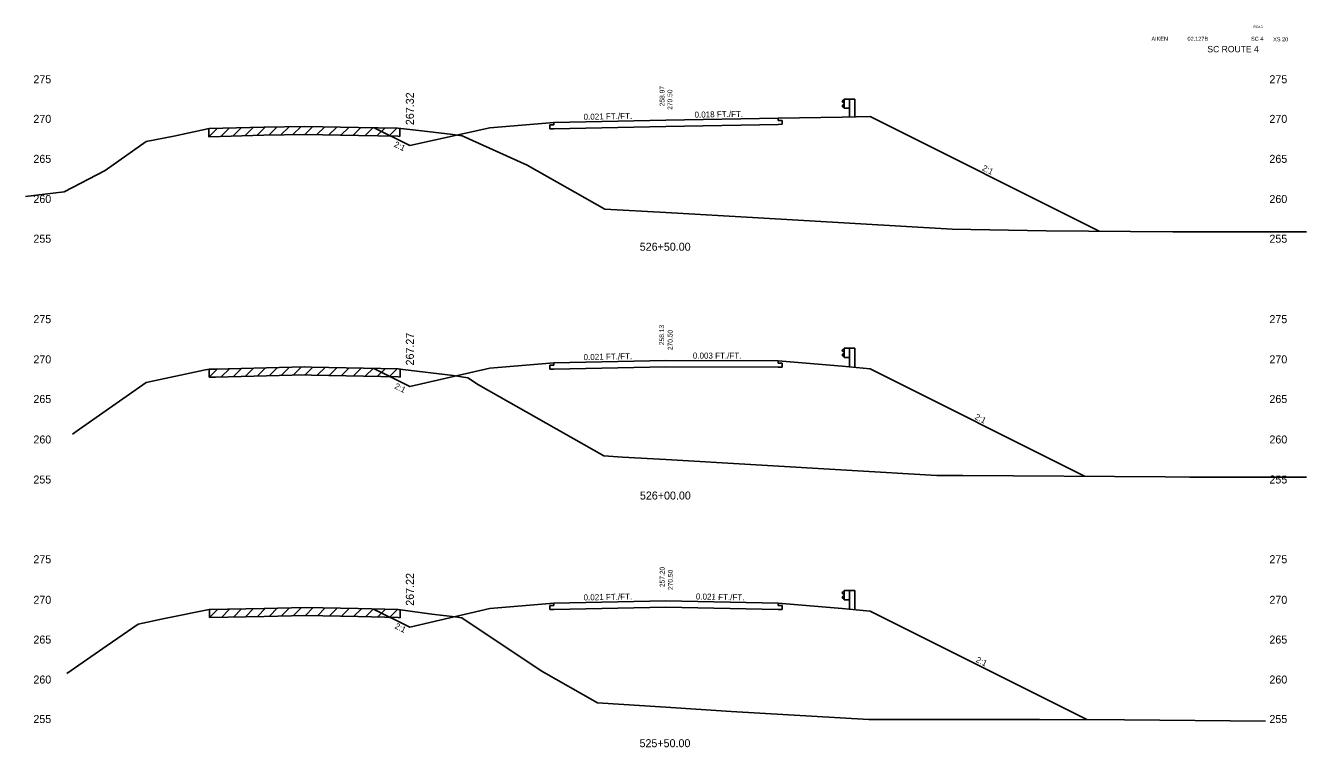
# Model space of a CAD drawing. Extents: x 883 to 1160, y 1002 to 4323.
# Drawn here: x 1000 to 1160, y 3197.2 to 3287.3 of the extents above; entities that cross this region are included whole.
import ezdxf

# ---------------------------------------------------------------- set-up
doc = ezdxf.new("R2010")
doc.units = 0
for name, color, linetype in [('Level 1', 7, 'Continuous'), ('Level 10', 7, 'Continuous'), ('Level 11', 7, 'Continuous'), ('Level 12', 7, 'Continuous'), ('Level 24', 7, 'Continuous'), ('Level 3', 7, 'Continuous'), ('Level 32', 7, 'Continuous'), ('Level 33', 7, 'Continuous'), ('Level 59', 7, 'Continuous'), ('Level 6', 7, 'Continuous'), ('Level 60', 7, 'Continuous'), ('Level 61', 7, 'Continuous'), ('Level 7', 7, 'Continuous')]:
    doc.layers.add(name, color=color, linetype=linetype)

msp = doc.modelspace()

# ---------------------------------------------------------------- linework, layer by layer
at = {"layer": 'Level 11'}
for p, q in [((1066, 3275.21), (1066, 3274.91)), ((1094, 3275.45), (1094, 3275.75)), ((1094.5, 3275.46), (1094, 3275.45)), ((1094.5, 3274.98), (1094.5, 3275.46)), ((1066, 3274.91), (1065.5, 3274.9)), ((1065.5, 3274.9), (1065.5, 3274.42)), ((1065.5, 3274.42), (1066, 3274.43)), ((1094, 3274.97), (1094.5, 3274.98)), ((1066, 3244.91), (1065.5, 3244.9)), ((1065.5, 3244.9), (1065.5, 3244.42)), ((1066, 3245.21), (1066, 3244.91)), ((1094, 3245.16), (1094, 3245.46)), ((1094.5, 3245.16), (1094, 3245.16)), ((1094.5, 3244.68), (1094.5, 3245.16)), ((1065.5, 3244.42), (1066, 3244.43)), ((1094, 3244.68), (1094.5, 3244.68)), ((1066, 3214.91), (1065.5, 3214.9)), ((1065.5, 3214.9), (1065.5, 3214.42)), ((1065.5, 3214.42), (1066, 3214.43)), ((1066, 3215.21), (1066, 3214.91)), ((1094, 3214.91), (1094, 3215.21)), ((1094.5, 3214.9), (1094, 3214.91)), ((1094, 3214.43), (1094.5, 3214.42)), ((1094.5, 3214.42), (1094.5, 3214.9))]:
    msp.add_line(p, q, dxfattribs=at)
at = {"layer": 'Level 12'}
for p, q in [((1080, 3274.72), (1066, 3274.43)), ((1094, 3274.97), (1080, 3274.72)), ((1080, 3244.72), (1066, 3244.43)), ((1094, 3244.68), (1080, 3244.72)), ((1080, 3214.72), (1066, 3214.43)), ((1094, 3214.43), (1080, 3214.72))]:
    msp.add_line(p, q, dxfattribs=at)
at = {"layer": 'Level 24'}
for p, q in [((1102.27, 3278.07), (1102, 3277.87)), ((1102, 3277.87), (1102, 3277.82)), ((1102, 3277.82), (1102.27, 3277.62)), ((1102, 3277.3), (1102.27, 3277.5)), ((1102, 3277.25), (1102, 3277.3)), ((1102.27, 3277.05), (1102, 3277.25)), ((1102.27, 3276.98), (1102.27, 3278.14)), ((1102.27, 3278.14), (1102.94, 3278.14)), ((1102.27, 3276.98), (1102.94, 3276.98)), ((1102.94, 3278.14), (1102.94, 3275.91)), ((1102.94, 3278.14), (1103.6, 3278.14)), ((1103.6, 3278.14), (1103.6, 3275.92)), ((1102.27, 3246.97), (1102, 3246.77)), ((1102, 3246.77), (1102, 3246.72)), ((1102, 3246.72), (1102.27, 3246.52)), ((1102.27, 3245.87), (1102.27, 3247.04)), ((1102.27, 3247.04), (1102.94, 3247.04)), ((1102.94, 3247.04), (1102.94, 3244.7)), ((1102.94, 3247.04), (1103.6, 3247.04)), ((1103.6, 3247.04), (1103.6, 3244.63)), ((1102, 3246.2), (1102.27, 3246.4)), ((1102, 3246.15), (1102, 3246.2)), ((1102.27, 3245.95), (1102, 3246.15)), ((1102.27, 3245.87), (1102.94, 3245.87)), ((1102.27, 3216.72), (1102, 3216.52)), ((1102, 3216.52), (1102, 3216.47)), ((1102, 3216.47), (1102.27, 3216.27)), ((1102, 3215.95), (1102.27, 3216.15)), ((1102.27, 3215.63), (1102.27, 3216.79)), ((1102.27, 3216.79), (1102.94, 3216.79)), ((1102.94, 3216.79), (1102.94, 3214.45)), ((1102.94, 3216.79), (1103.6, 3216.79)), ((1103.6, 3216.79), (1103.6, 3214.38)), ((1102, 3215.9), (1102, 3215.95)), ((1102.27, 3215.7), (1102, 3215.9)), ((1102.27, 3215.63), (1102.94, 3215.63))]:
    msp.add_line(p, q, dxfattribs=at)
at = {"layer": 'Level 59'}
for p, q in [((1066, 3275.21), (1080, 3275.5)), ((1080, 3275.5), (1094, 3275.75)), ((1066, 3245.21), (1080, 3245.5)), ((1080, 3245.5), (1094, 3245.46)), ((1066, 3215.21), (1080, 3215.5)), ((1080, 3215.5), (1094, 3215.21))]:
    msp.add_line(p, q, dxfattribs=at)
at = {"layer": 'Level 6'}
for p, q in [((1058, 3274.54), (1066, 3275.21)), ((1094, 3275.75), (1102, 3275.89)), ((1102, 3275.89), (1105.5, 3275.96)), ((1058, 3244.54), (1066, 3245.21)), ((1094, 3245.46), (1102, 3244.79)), ((1102, 3244.79), (1105.5, 3244.44)), ((1058, 3214.54), (1066, 3215.21)), ((1094, 3215.21), (1102, 3214.54)), ((1102, 3214.54), (1105.5, 3214.19))]:
    msp.add_line(p, q, dxfattribs=at)
at = {"layer": 'Level 60'}
for p, q in [((1018.52, 3273.51), (1022.92, 3274.44)), ((1022.92, 3274.44), (1029.75, 3274.61)), ((1029.75, 3274.61), (1034.9, 3274.73)), ((1034.9, 3274.73), (1041.6, 3274.58)), ((1041.6, 3274.58), (1046.5, 3274.5)), ((1046.5, 3274.5), (1049.48, 3274.16)), ((1049.48, 3274.16), (1053.37, 3273.7)), ((1053.37, 3273.7), (1054.52, 3273.53)), ((1009.93, 3269.23), (1015.08, 3272.84)), ((1015.08, 3272.84), (1018.52, 3273.51)), ((1054.52, 3273.53), (1062.67, 3269.87)), ((1004.81, 3266.54), (1009.93, 3269.23)), ((1062.67, 3269.87), (1072.36, 3264.4)), ((1000, 3265.99), (1004.81, 3266.54)), ((1072.36, 3264.4), (1080, 3263.97)), ((1080, 3263.97), (1091.5, 3263.32)), ((1091.5, 3263.32), (1115.77, 3261.9)), ((1115.77, 3261.9), (1127.49, 3261.69)), ((1127.49, 3261.69), (1143.33, 3261.57)), ((1143.33, 3261.57), (1154.78, 3261.57)), ((1154.78, 3261.57), (1160, 3261.57)), ((1015.07, 3242.76), (1022.25, 3244.27)), ((1022.25, 3244.27), (1022.91, 3244.4)), ((1022.91, 3244.4), (1023.74, 3244.42)), ((1023.74, 3244.42), (1034.89, 3244.7)), ((1034.89, 3244.7), (1035.71, 3244.68)), ((1035.71, 3244.68), (1046.56, 3244.44)), ((1046.56, 3244.44), (1047.11, 3244.36)), ((1047.11, 3244.36), (1053.4, 3243.62)), ((1053.4, 3243.62), (1055.25, 3243.34)), ((1055.25, 3243.34), (1056.57, 3242.46)), ((1006.75, 3236.93), (1015.07, 3242.76)), ((1056.57, 3242.46), (1072.24, 3233.6)), ((1005.84, 3236.3), (1006.75, 3236.93)), ((1072.24, 3233.6), (1074.55, 3233.45)), ((1074.55, 3233.45), (1080, 3233.13)), ((1080, 3233.13), (1113.82, 3231.15)), ((1113.82, 3231.15), (1117.08, 3231.16)), ((1117.08, 3231.16), (1142.36, 3230.97)), ((1142.36, 3230.97), (1145.43, 3230.95)), ((1145.43, 3230.95), (1160, 3230.95)), ((1022.93, 3214.4), (1029.79, 3214.55)), ((1029.79, 3214.55), (1034.94, 3214.68)), ((1034.94, 3214.68), (1041.54, 3214.52)), ((1041.54, 3214.52), (1046.56, 3214.41)), ((1046.56, 3214.41), (1050.76, 3213.82)), ((1014.04, 3212.6), (1017.36, 3213.3)), ((1017.36, 3213.3), (1022.93, 3214.4)), ((1050.76, 3213.82), (1053.65, 3213.48)), ((1053.65, 3213.48), (1054.49, 3213.36)), ((1054.49, 3213.36), (1064.39, 3206.76)), ((1010.19, 3209.91), (1014.04, 3212.6)), ((1005.16, 3206.43), (1010.19, 3209.91)), ((1064.39, 3206.76), (1071.45, 3202.76)), ((1071.45, 3202.76), (1080, 3202.2)), ((1080, 3202.2), (1088.15, 3201.66)), ((1088.15, 3201.66), (1105.32, 3200.66)), ((1105.32, 3200.66), (1126.68, 3200.7)), ((1126.68, 3200.7), (1137.28, 3200.62)), ((1137.28, 3200.62), (1154.91, 3200.49))]:
    msp.add_line(p, q, dxfattribs=at)
at = {"layer": 'Level 61'}
for p, q in [((1023.92, 3274.46), (1022.89, 3273.43)), ((1022.89, 3274.43), (1022.89, 3273.43)), ((1022.92, 3273.44), (1029.75, 3273.61)), ((1025.42, 3274.5), (1024.39, 3273.48)), ((1026.92, 3274.54), (1025.89, 3273.51)), ((1028.42, 3274.58), (1027.39, 3273.55)), ((1029.92, 3274.61), (1028.89, 3273.59)), ((1029.75, 3273.61), (1034.9, 3273.73)), ((1031.41, 3274.65), (1030.39, 3273.62)), ((1032.91, 3274.68), (1031.89, 3273.66)), ((1034.41, 3274.71), (1033.39, 3273.69)), ((1035.87, 3274.7), (1034.89, 3273.73)), ((1034.9, 3273.73), (1041.6, 3273.58)), ((1037.37, 3274.67), (1036.39, 3273.69)), ((1038.87, 3274.64), (1037.89, 3273.66)), ((1040.37, 3274.6), (1039.39, 3273.63)), ((1041.87, 3274.57), (1040.89, 3273.59)), ((1043.38, 3274.55), (1042.39, 3273.56)), ((1044.88, 3274.52), (1043.89, 3273.54)), ((1046.38, 3274.5), (1045.39, 3273.51)), ((1046.74, 3273.47), (1046.74, 3274.47)), ((1022.89, 3273.43), (1022.92, 3273.44)), ((1041.6, 3273.58), (1046.5, 3273.5)), ((1046.5, 3273.5), (1046.74, 3273.47)), ((1023.95, 3244.42), (1022.93, 3243.4)), ((1022.93, 3244.4), (1022.93, 3243.4)), ((1022.93, 3243.4), (1023.74, 3243.42)), ((1023.74, 3243.42), (1034.89, 3243.7)), ((1025.45, 3244.46), (1024.43, 3243.44)), ((1026.95, 3244.5), (1025.93, 3243.47)), ((1028.45, 3244.54), (1027.43, 3243.51)), ((1029.95, 3244.57), (1028.93, 3243.55)), ((1031.45, 3244.61), (1030.43, 3243.59)), ((1032.95, 3244.65), (1031.93, 3243.62)), ((1034.45, 3244.69), (1033.43, 3243.66)), ((1034.89, 3243.7), (1035.71, 3243.68)), ((1035.9, 3244.67), (1034.93, 3243.7)), ((1035.71, 3243.68), (1046.56, 3243.44)), ((1037.41, 3244.64), (1036.43, 3243.66)), ((1038.91, 3244.61), (1037.93, 3243.63)), ((1040.41, 3244.57), (1039.43, 3243.59)), ((1041.91, 3244.54), (1040.93, 3243.56)), ((1043.41, 3244.51), (1042.43, 3243.53)), ((1044.91, 3244.47), (1043.93, 3243.49)), ((1046.41, 3244.44), (1045.43, 3243.46)), ((1046.56, 3243.44), (1046.77, 3243.41)), ((1046.77, 3243.41), (1046.77, 3244.41)), ((1023.98, 3214.42), (1022.96, 3213.4)), ((1022.96, 3214.4), (1022.96, 3213.4)), ((1025.48, 3214.46), (1024.46, 3213.43)), ((1026.98, 3214.49), (1025.96, 3213.47)), ((1028.48, 3214.52), (1027.46, 3213.5)), ((1029.98, 3214.56), (1028.96, 3213.54)), ((1031.48, 3214.6), (1030.46, 3213.57)), ((1032.98, 3214.63), (1031.96, 3213.61)), ((1034.48, 3214.67), (1033.46, 3213.65)), ((1035.93, 3214.66), (1034.96, 3213.68)), ((1037.43, 3214.62), (1036.46, 3213.64)), ((1038.93, 3214.58), (1037.96, 3213.61)), ((1040.43, 3214.55), (1039.46, 3213.57)), ((1041.94, 3214.51), (1040.96, 3213.53)), ((1043.44, 3214.48), (1042.46, 3213.5)), ((1044.94, 3214.44), (1043.96, 3213.46)), ((1046.44, 3214.41), (1045.46, 3213.43)), ((1022.96, 3213.4), (1029.79, 3213.55)), ((1029.79, 3213.55), (1034.94, 3213.68)), ((1034.94, 3213.68), (1041.54, 3213.52)), ((1041.54, 3213.52), (1046.56, 3213.41)), ((1046.56, 3213.41), (1046.81, 3213.37)), ((1046.81, 3213.37), (1046.81, 3214.37))]:
    msp.add_line(p, q, dxfattribs=at)
at = {"layer": 'Level 7'}
for p, q in [((1105.5, 3275.96), (1134.13, 3261.64)), ((1043.54, 3274.54), (1048, 3272.32)), ((1048, 3272.32), (1058, 3274.54)), ((1043.52, 3244.5), (1048, 3242.27)), ((1048, 3242.27), (1058, 3244.54)), ((1105.5, 3244.44), (1132.29, 3231.05)), ((1043.48, 3214.47), (1048, 3212.22)), ((1048, 3212.22), (1058, 3214.54)), ((1105.5, 3214.19), (1132.57, 3200.66))]:
    msp.add_line(p, q, dxfattribs=at)

# ---------------------------------------------------------------- texts
at = {"layer": 'Level 1'}
for s, height, p in [('AIKEN', 0.5, (1140.64, 3285.41)), ('02.127B', 0.5, (1145.15, 3285.41)), ('SC 4', 0.5, (1153.09, 3285.41)), ('XS 20', 0.5, (1155.85, 3285.35)), ('SC ROUTE 4', 0.8, (1147.63, 3283.97)), ('526+50.00', 1, (1076.72, 3259.2)), ('526+00.00', 1, (1076.74, 3228.14)), ('525+50.00', 1, (1076.69, 3197.22))]:
    msp.add_text(s, height=height, dxfattribs=at).set_placement(p)
at = {"layer": 'Level 10'}
for s, p in [('258.97', (1079.81, 3277.23)), ('258.13', (1079.76, 3247.41)), ('257.20', (1079.82, 3217.21))]:
    msp.add_text(s, height=0.6, rotation=90, dxfattribs=at).set_placement(p)
at = {"layer": 'Level 3'}
for s, height, p in [('ROAD', 0.3, (1153.38, 3287)), (' 275', 1, (1000.6, 3280.11)), (' 275', 1, (1155.01, 3280.11)), (' 270', 1, (1000.6, 3275.16)), (' 270', 1, (1155.01, 3275.16)), (' 265', 1, (1000.6, 3270.17)), (' 265', 1, (1155.01, 3270.17)), (' 260', 1, (1000.6, 3265.16)), (' 260', 1, (1155.01, 3265.16)), (' 255', 1, (1000.6, 3260.2)), (' 255', 1, (1155.01, 3260.2)), (' 275', 1, (1000.6, 3250.16)), (' 275', 1, (1155.01, 3250.16)), (' 270', 1, (1000.6, 3245.14)), (' 270', 1, (1155.01, 3245.14)), (' 265', 1, (1000.6, 3240.19)), (' 265', 1, (1155.01, 3240.19)), (' 260', 1, (1000.6, 3235.14)), (' 260', 1, (1155.01, 3235.14)), (' 255', 1, (1000.6, 3230.14)), (' 255', 1, (1155.01, 3230.14)), (' 275', 1, (1000.6, 3220.19)), (' 275', 1, (1155.01, 3220.19)), (' 270', 1, (1000.6, 3215.12)), (' 270', 1, (1155.01, 3215.12)), (' 265', 1, (1000.6, 3210.16)), (' 265', 1, (1155.01, 3210.16)), (' 260', 1, (1000.6, 3205.17)), (' 260', 1, (1155.01, 3205.17)), (' 255', 1, (1000.6, 3200.24)), (' 255', 1, (1155.01, 3200.24))]:
    msp.add_text(s, height=height, dxfattribs=at).set_placement(p)
at = {"layer": 'Level 32'}
for s, rotation, p in [('0.021 FT./FT.', 1.1916, (1069.71, 3275.54)), ('0.018 FT./FT.', 1.0229, (1083.57, 3275.81)), ('2:1', 333.435, (1045.95, 3272.23)), ('2:1', 333.435, (1119.42, 3269.28)), ('0.021 FT./FT.', 1.1916, (1069.71, 3245.54)), ('0.003 FT./FT.', 359.8303, (1083.35, 3245.74)), ('2:1', 333.435, (1046.01, 3242.05)), ('2:1', 333.435, (1118.5, 3238.22)), ('0.021 FT./FT.', 1.1916, (1069.71, 3215.54)), ('0.021 FT./FT.', 358.8084, (1083.72, 3215.67)), ('2:1', 333.435, (1046.04, 3212.1)), ('2:1', 333.435, (1118.64, 3207.9))]:
    msp.add_text(s, height=0.75, rotation=rotation, dxfattribs=at).set_placement(p)
at = {"layer": 'Level 33'}
for s, p in [('267.32', (1048.5, 3274.88)), ('267.27', (1048.5, 3244.88)), ('267.22', (1048.5, 3214.88))]:
    msp.add_text(s, height=1, rotation=90, dxfattribs=at).set_placement(p)
at = {"layer": 'Level 59'}
for p in [(1080.79, 3276.56), (1080.82, 3246.56), (1080.85, 3216.62)]:
    msp.add_text(' 270.50', height=0.6, rotation=90, dxfattribs=at).set_placement(p)

doc.saveas('drawing.dxf')
